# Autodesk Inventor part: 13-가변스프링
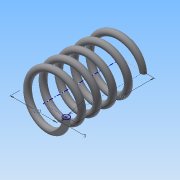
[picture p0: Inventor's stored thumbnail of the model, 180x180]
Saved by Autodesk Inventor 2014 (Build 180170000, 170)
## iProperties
Created: 2015-09
Part Number: 13-가변스프링
Material: 강철, 탄소
Document SubType Name: Modeling
Designer: study
Density: 7.87 g/cm^3
Appearance: 반연마
Mass: 18.8817 g
Surface Area: 32.5359 cm^2
Volume: 2.3992 cm^3
Author: study
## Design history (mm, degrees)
sketch "스케치1"
  geometry: L1 (0, 0)-(11, 0); L2 (11, 0)-(11, 36.261); L3 (11, 36.261)-(0, 36.261); L4 (0, 36.261)-(0, 0); C1 r 1.5 at (11, 0)
  constraints: 8 end point, 2 parallel, 1 centre point, 1 coincident, 1 horizontal, 1 perpendicular
  dimensions: "d0" = 3 diameter of C1; "d1" = 22 diameter of L1.end L4; "d2" = 36.2612 distance of L1.end L2.end (derived)
feature "코일1" sketch "스케치1" pitch "d3" = 10; turns "d5" = 5; dims "d4" = 36.2612 (= d2), "d6" = 0, angle "d7" = 90 deg, angle "d8" = 90 deg, "d9" = 0, "d10" = 0
node "작업 평면1"
sketch "스케치2"
  geometry: L1 (-12.5, 0)-(-9.5, 0) reference; 1 further point
  constraints: 1 horizontal alignment
extrude "돌출1" cut sketch "스케치2" stored distance "d12" = 10; taper "d13" = 0 deg
node "작업 평면2"
sketch "스케치3"
  geometry: L1 (-9.5, 0)-(-12.5, 0) reference; 1 further point
  constraints: 1 horizontal alignment
extrude "돌출2" cut sketch "스케치3" stored distance "d15" = 10; taper "d16" = 0 deg
node "솔리드1"
node "절단 모서리 투영1"
node "절단 모서리 투영2"
other parameters: "d11" = 0, "d14" = 36.2612 (= d2)
